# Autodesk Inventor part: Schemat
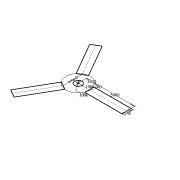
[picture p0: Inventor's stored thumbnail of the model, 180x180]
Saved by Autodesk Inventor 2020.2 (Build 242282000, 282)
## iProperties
Created: 2006-01
Part Number: Schemat
Document SubType Name: Modeling
Designer: F.Stasiak
Density: 1 g/cm^3
Material: Ogólny
Appearance: Domyślna
Manager: www.cadconsulting.pl
Company: Fabian Stasiak CAD Consulting
Author: F.Stasiak
Subject: Zbiór ćwiczeń. Autodesk Inventor 2020. Kurs podstawowy
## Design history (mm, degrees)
sketch "Szkic1"
  geometry: L1 (1500, 620)-(6560, 620); L2 (6560, 620)-(6560, -620); L3 (6560, -620)-(1500, -620); L4 (1500, -620)-(1500, 620); L5 (1500, 0)-(6560, 0); L6 (-1286.936, 989.038)-(-3816.936, 5371.127); L7 (-3816.936, 5371.127)-(-2743.064, 5991.127); L8 (-2743.064, 5991.127)-(-213.064, 1609.038); L9 (-213.064, 1609.038)-(-1286.936, 989.038); L10 (-750, 1299.038)-(-3280, 5681.127); L11 (-213.064, -1609.038)-(-2743.064, -5991.127); L12 (-2743.064, -5991.127)-(-3816.936, -5371.127); L13 (-3816.936, -5371.127)-(-1286.936, -989.038); L14 (-1286.936, -989.038)-(-213.064, -1609.038); L15 (-750, -1299.038)-(-3280, -5681.127); C1 r 500 at (0, 0); 1 further point
  constraints: 30 end point, 2 midpoint, 2 parallel, 1 centre point, 1 coincident, 1 horizontal, 1 perpendicular, 34 other
  dimensions: "d0" = 1000 diameter of C1; "d1" = 5060 distance of L1.start L1.end; "d2" = 1240 distance of L1.end L2.end; "d3" = 1500 distance from line of L4 point (0, 0); "d4" = 0 distance from line of L5 C1.centre; "d7" = 360 deg dimension on point (0, 0) L1.start (derived)
node "Korpusy bryłowe"
node "Korpusy powierzchniowe"
